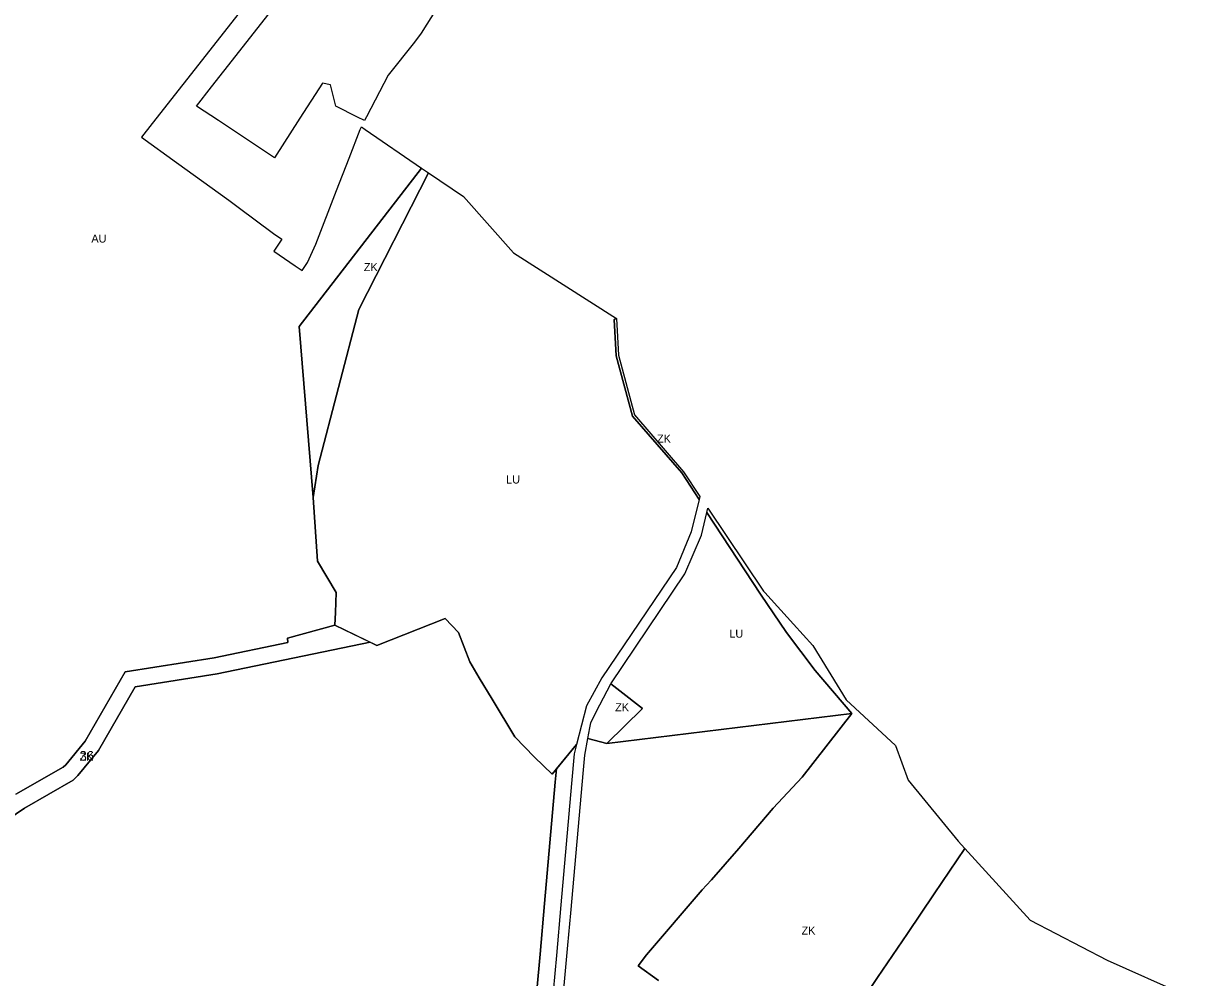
# Model space of a CAD drawing. Extents: x -521261 to -517465, y -1182764 to -1179456.
# Drawn here: x -518978 to -518263, y -1181423 to -1180835 of the extents above; entities that cross this region are included whole.
import ezdxf

# ---------------------------------------------------------------- set-up
doc = ezdxf.new("R2010")
doc.units = 0
for name, color, linetype in [('90710013', 7, 'Continuous'), ('90710023', 7, 'Continuous'), ('90750013', 7, 'Continuous'), ('90770013', 7, 'Continuous'), ('ID_navrh', 7, 'Continuous')]:
    doc.layers.add(name, color=color, linetype=linetype)

msp = doc.modelspace()

# ---------------------------------------------------------------- linework, layer by layer
at = {"layer": '90710013'}
for points in [[(-518808.38, -1181021.86), (-518732.905, -1180924.262), (-518728.61, -1180927.2), (-518771.62, -1181011.43), (-518796.51, -1181107.45), (-518799.71, -1181127.22)], [(-518603.1, -1181077.1), (-518613.17, -1181039.84), (-518614.4, -1181017.6), (-518612.92, -1181016.94), (-518611.72, -1181039.62), (-518601.93, -1181076.25), (-518571.79, -1181111.44), (-518561.65, -1181126.57), (-518562.06, -1181128.41), (-518572.75, -1181111.95)], [(-518630.55, -1181275.53), (-518629.36, -1181269.07), (-518628.78, -1181265.87), (-518625.43, -1181259.15), (-518616.48, -1181241.98), (-518610.97, -1181246.25), (-518597, -1181257.08), (-518618.91, -1181278.73)]]:
    msp.add_lwpolyline(points, close=True, dxfattribs=at)
msp.add_lwpolyline([(-518587.17, -1181424.75), (-518599.62, -1181415.62), (-518594.4, -1181408.92), (-518560.15, -1181368.8), (-518557.46, -1181365.95), (-518554.51, -1181362.62), (-518537.66, -1181343.4), (-518516.46, -1181318.54), (-518498.65, -1181299.5), (-518468.13, -1181260.3), (-518490.58, -1181233.66), (-518508.25, -1181210.43), (-518524.34, -1181186.8), (-518557.39, -1181136.36), (-518556.81, -1181133.74), (-518522.41, -1181184.93), (-518521.66, -1181185.76), (-518503.98, -1181205.23), (-518492.13, -1181218.29), (-518471.48, -1181251.81), (-518441.26, -1181279.93), (-518433.35, -1181301.32), (-518402.58, -1181338.76), (-518398.47, -1181343.3), (-518417.38, -1181371.29), (-518433.91, -1181395.73), (-518452.27, -1181422.89), (-518461.77, -1181436.96)], dxfattribs=at)
at = {"layer": '90710023'}
for points in [[(-518982.66, -1181309.99), (-518953.51, -1181293.31), (-518952.02, -1181291.79), (-518939.99, -1181277.22), (-518915.45, -1181234.59), (-518860.62, -1181225.98), (-518815.3, -1181216.55), (-518815.46, -1181213.78), (-518786.29, -1181205.72), (-518764.658, -1181216.227), (-518858.825, -1181235.821), (-518909.171, -1181243.727), (-518931.743, -1181282.938), (-518944.58, -1181298.486), (-518947.34, -1181301.301), (-518977.383, -1181318.492), (-519004.519, -1181336.714)], [(-518661.886, -1181430.802), (-518659.932, -1181408.429), (-518657.202, -1181377.258), (-518650.652, -1181302.406), (-518649.942, -1181294.328), (-518637.63, -1181279.33), (-518639.08, -1181284.96), (-518640.69, -1181303.28), (-518647.24, -1181378.13), (-518649.97, -1181409.3), (-518651.9, -1181431.4)]]:
    msp.add_lwpolyline(points, dxfattribs=at)
at = {"layer": '90750013'}
for points in [[(-518811.46, -1180785.47), (-518879.81, -1180872.74), (-518898.78, -1180896.9), (-518905.31, -1180905.29), (-518883.79, -1180920.87), (-518851.55, -1180944.12), (-518845.75, -1180948.41), (-518824.07, -1180964.69), (-518819.03, -1180968), (-518823.9, -1180975.55), (-518810.67, -1180984.43), (-518806.398, -1180987.297), (-518803.2, -1180982.47), (-518797.94, -1180971.15), (-518785.21, -1180938.18), (-518777.5, -1180918.25), (-518770.69, -1180900.6), (-518770.01, -1180898.85), (-518767.65, -1180900.49), (-518732.905, -1180924.262), (-518808.38, -1181021.86), (-518799.71, -1181127.22), (-518796.94, -1181166.4), (-518785.42, -1181185.66), (-518785.86, -1181197.97), (-518786.29, -1181205.72), (-518815.46, -1181213.78), (-518815.3, -1181216.55), (-518860.62, -1181225.98), (-518915.45, -1181234.59), (-518939.99, -1181277.22), (-518952.02, -1181291.79), (-518953.51, -1181293.31), (-518982.66, -1181309.99)], [(-518699.96, -1180788.29), (-518733.13, -1180841.32), (-518737.39, -1180846.67), (-518753.55, -1180867.09), (-518766.86, -1180892.78), (-518768.05, -1180895.07), (-518772.34, -1180892.89), (-518785.65, -1180886.11), (-518789.09, -1180873.05), (-518793.95, -1180872.06), (-518807.86, -1180893.62), (-518823.56, -1180917.96), (-518857.86, -1180895.06), (-518871.4, -1180886.12), (-518862.16, -1180874.22), (-518847.08, -1180854.98), (-518802.83, -1180798.37)], [(-519004.519, -1181336.714), (-518977.383, -1181318.492), (-518947.34, -1181301.301), (-518944.58, -1181298.486), (-518931.743, -1181282.938), (-518909.171, -1181243.727), (-518858.825, -1181235.821), (-518764.658, -1181216.227), (-518760.41, -1181218.29), (-518718.38, -1181201.7), (-518710.23, -1181210.23), (-518703.33, -1181228.32), (-518697.49, -1181238.21), (-518689.45, -1181251.43), (-518675.54, -1181274.63), (-518663.33, -1181287.08), (-518652.62, -1181297.59), (-518649.942, -1181294.328), (-518650.652, -1181302.406), (-518657.202, -1181377.258), (-518659.932, -1181408.429), (-518661.886, -1181430.802)], [(-518645.49, -1181432.17), (-518642.96, -1181402.9), (-518641.12, -1181383.21), (-518633.23, -1181294.88), (-518632.43, -1181285.85), (-518630.55, -1181275.53), (-518618.91, -1181278.73), (-518468.13, -1181260.3), (-518498.65, -1181299.5), (-518516.46, -1181318.54), (-518537.66, -1181343.4), (-518554.51, -1181362.62), (-518557.46, -1181365.95), (-518560.15, -1181368.8), (-518594.4, -1181408.92), (-518599.62, -1181415.62), (-518587.17, -1181424.75)], [(-518461.77, -1181436.96), (-518452.27, -1181422.89), (-518433.91, -1181395.73), (-518417.38, -1181371.29), (-518398.47, -1181343.3), (-518358.32, -1181387.58), (-518310.97, -1181412.15), (-518263.14, -1181433.58)]]:
    msp.add_lwpolyline(points, dxfattribs=at)
at = {"layer": '90770013'}
for points in [[(-518652.62, -1181297.59), (-518663.33, -1181287.08), (-518675.54, -1181274.63), (-518689.45, -1181251.43), (-518697.49, -1181238.21), (-518703.33, -1181228.32), (-518710.23, -1181210.23), (-518718.38, -1181201.7), (-518760.41, -1181218.29), (-518786.29, -1181205.72), (-518785.86, -1181197.97), (-518785.42, -1181185.66), (-518796.94, -1181166.4), (-518799.71, -1181127.22), (-518796.51, -1181107.45), (-518771.62, -1181011.43), (-518728.61, -1180927.2), (-518707.17, -1180941.87), (-518676.44, -1180976.47), (-518612.92, -1181016.94), (-518614.4, -1181017.6), (-518613.17, -1181039.84), (-518603.1, -1181077.1), (-518572.75, -1181111.95), (-518562.06, -1181128.41), (-518566.98, -1181148.39), (-518576.06, -1181170.33), (-518621.98, -1181238.21), (-518631.51, -1181255.55), (-518637.63, -1181279.33)], [(-518618.91, -1181278.73), (-518597, -1181257.08), (-518610.97, -1181246.25), (-518616.48, -1181241.98), (-518570.97, -1181174.25), (-518560.63, -1181150.29), (-518557.39, -1181136.36), (-518524.34, -1181186.8), (-518508.25, -1181210.43), (-518490.58, -1181233.66), (-518468.13, -1181260.3)]]:
    msp.add_lwpolyline(points, close=True, dxfattribs=at)

# ---------------------------------------------------------------- texts
at = {"layer": '90710013'}
for rotation, p in [(0, (-518768.495, -1180987.797)), (0, (-518588.025, -1181093.447)), (360, (-518613.775, -1181258.866)), (360, (-518499.045, -1181396.4))]:
    msp.add_text('ZK', height=5, rotation=rotation, dxfattribs=at).set_placement(p)
at = {"layer": '90710023'}
msp.add_text('ZK', height=5, rotation=0, dxfattribs=at).set_placement((-518943.479, -1181289.299))
at = {"layer": '90750013'}
msp.add_text('AU', height=5, rotation=0, dxfattribs=at).set_placement((-518936.2, -1180970.228))
at = {"layer": '90770013'}
for rotation, p in [(360, (-518680.885, -1181118.59)), (0, (-518543.52, -1181213.522))]:
    msp.add_text('LU', height=5, rotation=rotation, dxfattribs=at).set_placement(p)
at = {"layer": 'ID_navrh'}
msp.add_text('36', height=6, rotation=360, dxfattribs=at).set_placement((-518943.479, -1181289.299))

doc.saveas('drawing.dxf')
